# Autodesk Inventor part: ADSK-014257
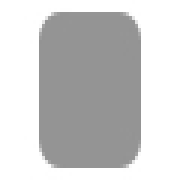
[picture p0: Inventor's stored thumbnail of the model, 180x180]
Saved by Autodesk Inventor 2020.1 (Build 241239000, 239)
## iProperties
Created: 2019-01
Part Number: ADSK-014257
Material: Stahl, weich
Document SubType Name: Modeling
Designer: lutzd
Language: de-DE
Size Designation: 5 x 39,384472 x 39,384472
Categories: <MemberInstance><Categories><Category DisplayName="Sonstige Bauteile" InternalName="5aa15e00-363f-49f2-933f-16f664388e3f" Mnemonic="OTHER"><Category DisplayName
Mass: 60.0398 g
Surface Area: 38.0412 cm^2
Volume: 7.64838 cm^3
Density: 7.85 g/cm^3
Appearance: Semi-Polished(8)
IsCustomPart: 1
Title: end cap
Author: lutzd
Revision Number: -
Dimensions: 39,4x39,4x5 mm
Mass: 0,06 kg
DocNumber: ADSK-014257
Folder: 01 - Themengebiete\Simplification\01 - Packaging machine\ADSK-014200\Frame\
VDS_Category: 3D Komponenten
VDS_NumSchm: Autodesk
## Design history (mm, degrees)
sketch "Sketch1"
  geometry: L1 (0, 20.175)-(0, -21.446); L2 (-20.203, 0)-(20.169, 0); L3 (-19.692, 19.692)-(19.692, 19.692); L4 (19.692, 19.692)-(19.692, -19.692); L5 (19.692, -19.692)-(-19.692, -19.692); L6 (-19.692, -19.692)-(-19.692, 19.692); 1 further point
  constraints: 12 end point, 2 horizontal, 2 parallel, 2 point on line, 1 perpendicular, 1 vertical
  dimensions: "d0" = 39.38447 distance between parallel lines of L5 L3 (= height); "d1" = 19.69224 distance between parallel lines of L2 L3 (= 0.5 x height); "d2" = 39.38447 distance between parallel lines of L6 L4 (= width); "d3" = 19.69224 distance between parallel lines of L6 L1 (= 0.5 x width)
extrude "Extrusion1" new body sketch "Sketch1" distance "d4" = 5 (= thickness); taper "d5" = 0 deg
fillet "Fillet1" dims "d6" = 5 (= fillet), "d7" = 0, "fillet" = 5 [user parameter; used in 1 equation term]
chamfer "Chamfer1" distance "d8" = 0 (computed from chamfer); stored, may be unused: second distance "d9" = 2, angle "d10" = 45 deg; dims "d11" = 0, "chamfer" = 0 [user parameter; used in 1 equation term]
body "Solid1"
other parameters: "thickness" = 5 [user parameter; used in 1 equation term], "width" = 39.38447 [user parameter; used in 2 equation terms], "height" = 39.38447 [user parameter; used in 2 equation terms]
